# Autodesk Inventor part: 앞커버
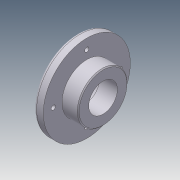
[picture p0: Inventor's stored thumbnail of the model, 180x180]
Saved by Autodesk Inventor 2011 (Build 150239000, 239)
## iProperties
Company: 한국ATC센터
Created: 2014-11
Part Number: 앞커버
Document SubType Name: Modeling
Designer: KYOUNG IL JANG
Density: 2.71 g/cm^3
Material: 알루미늄-6061
Mass: 204.895 g
Surface Area: 201.401 cm^2
Volume: 75.6071 cm^3
Author: KYOUNG IL JANG
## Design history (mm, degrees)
sketch "스케치1"
  geometry: L1 (-13.5, 0)-(13.5, 0); L2 (-13.5, 0)-(-13.5, 45.5); L3 (-13.5, 45.5)-(-3.5, 45.5); L4 (-3.5, 45.5)-(-3.5, 26); L5 (-3.5, 26)-(13.5, 26); L6 (13.5, 26)-(13.5, 0); 2 further points
  constraints: 12 end point, 3 parallel, 2 perpendicular, 1 coincident, 1 horizontal, 1 midpoint
  dimensions: "d0" = 27 distance of L1.start L1.end; "d1" = 91 diameter of L3 L1; "d2" = 52 diameter of L5 L1; "d3" = 10 distance of L2.end L3.end
revolve "회전1" sketch "스케치1" stored, may be unused: angle "d4" = 90 deg
hole "구멍1" diameter "d7" = 30; stored, may be unused: countersink angle "d11" = 90 deg, drill point angle "d13" = 118 deg; dims "d5" = 10, "d6" = 10, "d8" = 6, "d9" = 40, "d10" = 8.3, "d12" = 8
sketch "스케치2"
  geometry: 2 further points
  constraints: 1 vertical alignment
  dimensions: "d14" = 35 distance of point (0, 0) point (0, 35)
hole "구멍2" sketch "스케치2" at (0, 35) diameter "d15" = 4.5; stored, may be unused: countersink angle "d19" = 90 deg, drill point angle "d21" = 118 deg; dims "d16" = 6, "d17" = 8, "d18" = 4.4, "d20" = 8
chamfer "모따기1" distance "d25" = 0.8; stored, may be unused: second distance "d26" = 2, angle "d27" = 30 deg
fillet "모깎기1" dims "d28" = 0.3, "d29" = 3
chamfer "모따기2" distance "d30" = 1; stored, may be unused: second distance "d31" = 2, angle "d32" = 30 deg
node "솔리드1"
pattern_circular "원형 패턴1" dims angle "d23" = 360 deg
